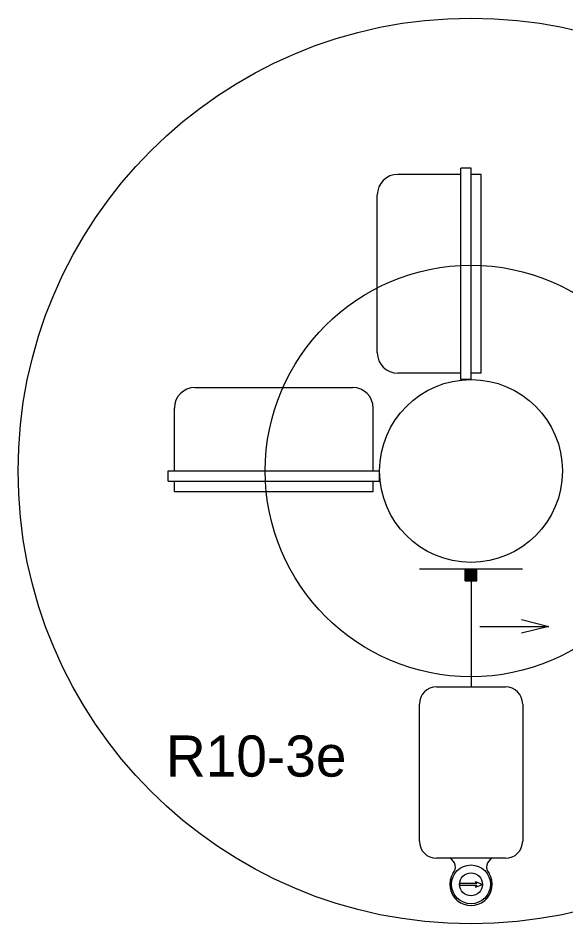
# Model space of a CAD drawing. Extents: x 1369885 to 1370886, y 379976 to 380616.
# Drawn here: x 1370603.9 to 1370663.8, y 380265.3 to 380364.3 of the extents above; entities that cross this region are included whole.
import ezdxf

# ---------------------------------------------------------------- set-up
doc = ezdxf.new("R2010")
doc.units = 0
doc.layers.add('T_Drafting', color=7, linetype='Continuous')

msp = doc.modelspace()

# ---------------------------------------------------------------- linework, layer by layer
at = {"layer": 'T_Drafting'}
for p, q in [((1370652.287, 380347.236), (1370645.412, 380347.236)), ((1370652.287, 380324.799), (1370652.287, 380347.924)), ((1370653.412, 380347.924), (1370652.287, 380347.924)), ((1370653.412, 380324.799), (1370653.412, 380347.924)), ((1370654.537, 380347.236), (1370653.412, 380347.236)), ((1370654.537, 380325.486), (1370654.537, 380347.236)), ((1370643.162, 380327.736), (1370643.162, 380344.986)), ((1370652.287, 380325.486), (1370645.412, 380325.486)), ((1370654.537, 380325.486), (1370653.412, 380325.486)), ((1370653.412, 380324.799), (1370652.287, 380324.799)), ((1370623.225, 380323.924), (1370640.475, 380323.924)), ((1370620.975, 380314.799), (1370620.975, 380321.674)), ((1370642.725, 380314.799), (1370642.725, 380321.674)), ((1370620.287, 380314.799), (1370643.412, 380314.799)), ((1370620.287, 380313.674), (1370620.287, 380314.799)), ((1370643.412, 380313.674), (1370643.412, 380314.799)), ((1370620.287, 380313.674), (1370643.412, 380313.674)), ((1370620.975, 380312.549), (1370620.975, 380313.674)), ((1370642.725, 380312.549), (1370642.725, 380313.674)), ((1370620.975, 380312.549), (1370642.725, 380312.549)), ((1370659.037, 380304.049), (1370647.787, 380304.049)), ((1370652.787, 380302.799), (1370652.787, 380304.049)), ((1370652.787, 380302.808), (1370654.028, 380304.049)), ((1370652.787, 380302.829), (1370654.007, 380304.049)), ((1370652.787, 380302.85), (1370653.986, 380304.049)), ((1370652.787, 380302.871), (1370653.965, 380304.049)), ((1370652.787, 380302.892), (1370653.943, 380304.049)), ((1370652.787, 380302.914), (1370653.922, 380304.049)), ((1370652.787, 380302.935), (1370653.901, 380304.049)), ((1370652.787, 380302.956), (1370653.88, 380304.049)), ((1370652.787, 380302.977), (1370653.859, 380304.049)), ((1370652.787, 380302.998), (1370653.837, 380304.049)), ((1370652.787, 380303.02), (1370653.816, 380304.049)), ((1370652.787, 380303.041), (1370653.795, 380304.049)), ((1370652.787, 380303.062), (1370653.774, 380304.049)), ((1370652.787, 380303.083), (1370653.752, 380304.049)), ((1370652.787, 380303.105), (1370653.731, 380304.049)), ((1370652.787, 380303.126), (1370653.71, 380304.049)), ((1370652.787, 380303.147), (1370653.689, 380304.049)), ((1370652.787, 380303.168), (1370653.668, 380304.049)), ((1370652.787, 380303.189), (1370653.646, 380304.049)), ((1370652.787, 380303.211), (1370653.625, 380304.049)), ((1370652.787, 380303.232), (1370653.604, 380304.049)), ((1370652.787, 380303.253), (1370653.583, 380304.049)), ((1370652.787, 380303.274), (1370653.562, 380304.049)), ((1370652.787, 380303.295), (1370653.54, 380304.049)), ((1370652.787, 380303.317), (1370653.519, 380304.049)), ((1370652.787, 380303.338), (1370653.498, 380304.049)), ((1370652.787, 380303.359), (1370653.477, 380304.049)), ((1370652.787, 380303.38), (1370653.455, 380304.049)), ((1370652.787, 380303.401), (1370653.434, 380304.049)), ((1370652.787, 380303.423), (1370653.413, 380304.049)), ((1370652.787, 380303.444), (1370653.392, 380304.049)), ((1370652.787, 380303.465), (1370653.371, 380304.049)), ((1370652.787, 380303.486), (1370653.349, 380304.049)), ((1370652.787, 380303.508), (1370653.328, 380304.049)), ((1370652.787, 380303.529), (1370653.307, 380304.049)), ((1370652.787, 380303.55), (1370653.286, 380304.049)), ((1370652.787, 380303.571), (1370653.265, 380304.049)), ((1370652.787, 380303.592), (1370653.243, 380304.049)), ((1370652.787, 380303.614), (1370653.222, 380304.049)), ((1370652.787, 380303.635), (1370653.201, 380304.049)), ((1370652.787, 380303.656), (1370653.18, 380304.049)), ((1370652.787, 380303.677), (1370653.158, 380304.049)), ((1370652.787, 380303.698), (1370653.137, 380304.049)), ((1370652.787, 380303.72), (1370653.116, 380304.049)), ((1370652.787, 380303.741), (1370653.095, 380304.049)), ((1370652.787, 380303.762), (1370653.074, 380304.049)), ((1370652.787, 380303.783), (1370653.052, 380304.049)), ((1370652.787, 380303.805), (1370653.031, 380304.049)), ((1370652.787, 380303.826), (1370653.01, 380304.049)), ((1370652.787, 380303.847), (1370652.989, 380304.049)), ((1370652.787, 380303.868), (1370652.968, 380304.049)), ((1370652.787, 380303.889), (1370652.946, 380304.049)), ((1370652.787, 380303.911), (1370652.925, 380304.049)), ((1370652.787, 380303.932), (1370652.904, 380304.049)), ((1370652.787, 380303.953), (1370652.883, 380304.049)), ((1370652.787, 380303.974), (1370652.861, 380304.049)), ((1370652.787, 380303.995), (1370652.84, 380304.049)), ((1370652.787, 380304.017), (1370652.819, 380304.049)), ((1370652.787, 380304.038), (1370652.798, 380304.049)), ((1370652.799, 380302.799), (1370654.037, 380304.036)), ((1370652.821, 380302.799), (1370654.037, 380304.015)), ((1370652.842, 380302.799), (1370654.037, 380303.994)), ((1370652.863, 380302.799), (1370654.037, 380303.973)), ((1370652.884, 380302.799), (1370654.037, 380303.951)), ((1370652.906, 380302.799), (1370654.037, 380303.93)), ((1370652.927, 380302.799), (1370654.037, 380303.909)), ((1370652.948, 380302.799), (1370654.037, 380303.888)), ((1370652.969, 380302.799), (1370654.037, 380303.867)), ((1370652.99, 380302.799), (1370654.037, 380303.845)), ((1370653.012, 380302.799), (1370654.037, 380303.824)), ((1370653.033, 380302.799), (1370654.037, 380303.803)), ((1370653.054, 380302.799), (1370654.037, 380303.782)), ((1370653.075, 380302.799), (1370654.037, 380303.761)), ((1370653.096, 380302.799), (1370654.037, 380303.739)), ((1370653.118, 380302.799), (1370654.037, 380303.718)), ((1370653.139, 380302.799), (1370654.037, 380303.697)), ((1370653.16, 380302.799), (1370654.037, 380303.676)), ((1370653.181, 380302.799), (1370654.037, 380303.654)), ((1370654.037, 380302.799), (1370654.037, 380304.049)), ((1370652.787, 380302.799), (1370654.037, 380302.799)), ((1370653.202, 380302.799), (1370654.037, 380303.633)), ((1370653.224, 380302.799), (1370654.037, 380303.612)), ((1370653.245, 380302.799), (1370654.037, 380303.591)), ((1370653.266, 380302.799), (1370654.037, 380303.57)), ((1370653.287, 380302.799), (1370654.037, 380303.548)), ((1370653.309, 380302.799), (1370654.037, 380303.527)), ((1370653.33, 380302.799), (1370654.037, 380303.506)), ((1370653.351, 380302.799), (1370654.037, 380303.485)), ((1370653.372, 380302.799), (1370654.037, 380303.464)), ((1370653.393, 380302.799), (1370654.037, 380303.442)), ((1370653.412, 380302.799), (1370653.412, 380291.194)), ((1370653.415, 380302.799), (1370654.037, 380303.421)), ((1370653.436, 380302.799), (1370654.037, 380303.4)), ((1370653.457, 380302.799), (1370654.037, 380303.379)), ((1370653.478, 380302.799), (1370654.037, 380303.357)), ((1370653.499, 380302.799), (1370654.037, 380303.336)), ((1370653.521, 380302.799), (1370654.037, 380303.315)), ((1370653.542, 380302.799), (1370654.037, 380303.294)), ((1370653.563, 380302.799), (1370654.037, 380303.273)), ((1370653.584, 380302.799), (1370654.037, 380303.251)), ((1370653.606, 380302.799), (1370654.037, 380303.23)), ((1370653.627, 380302.799), (1370654.037, 380303.209)), ((1370653.648, 380302.799), (1370654.037, 380303.188)), ((1370653.669, 380302.799), (1370654.037, 380303.167)), ((1370653.69, 380302.799), (1370654.037, 380303.145)), ((1370653.712, 380302.799), (1370654.037, 380303.124)), ((1370653.733, 380302.799), (1370654.037, 380303.103)), ((1370653.754, 380302.799), (1370654.037, 380303.082)), ((1370653.775, 380302.799), (1370654.037, 380303.061)), ((1370653.796, 380302.799), (1370654.037, 380303.039)), ((1370653.818, 380302.799), (1370654.037, 380303.018)), ((1370653.839, 380302.799), (1370654.037, 380302.997)), ((1370653.86, 380302.799), (1370654.037, 380302.976)), ((1370653.881, 380302.799), (1370654.037, 380302.954)), ((1370653.903, 380302.799), (1370654.037, 380302.933)), ((1370653.924, 380302.799), (1370654.037, 380302.912)), ((1370653.945, 380302.799), (1370654.037, 380302.891)), ((1370653.966, 380302.799), (1370654.037, 380302.87)), ((1370653.987, 380302.799), (1370654.037, 380302.848)), ((1370654.009, 380302.799), (1370654.037, 380302.827)), ((1370654.03, 380302.799), (1370654.037, 380302.806)), ((1370654.379, 380297.797), (1370661.928, 380297.797)), ((1370649.638, 380291.194), (1370657.187, 380291.194)), ((1370647.763, 380274.319), (1370647.763, 380289.319)), ((1370659.062, 380289.319), (1370659.062, 380274.319)), ((1370657.187, 380272.444), (1370649.638, 380272.444)), ((1370652.171, 380269.707), (1370652.171, 380269.482)), ((1370654.053, 380269.707), (1370652.171, 380269.707)), ((1370654.053, 380269.482), (1370652.171, 380269.482)), ((1370653.903, 380269.894), (1370654.662, 380269.594)), ((1370654.053, 380269.707), (1370653.903, 380269.894)), ((1370653.903, 380269.294), (1370654.662, 380269.594)), ((1370653.903, 380269.294), (1370654.053, 380269.482))]:
    msp.add_line(p, q, dxfattribs=at)
msp.add_lwpolyline([(1370658.928, 380298.547), (1370661.928, 380297.797), (1370658.928, 380297.047)], dxfattribs=at)
for centre, radius in [((1370653.412, 380314.799), 49.525), ((1370653.412, 380314.799), 22.5), ((1370653.412, 380314.799), 10), ((1370653.412, 380269.594), 2.125), ((1370653.412, 380269.594), 1.25)]:
    msp.add_circle(centre, radius, dxfattribs=at)
for centre, radius, start, end in [((1370645.412, 380344.986), 2.25, 90, 180), ((1370645.412, 380327.736), 2.25, 180, 270), ((1370623.225, 380321.674), 2.25, 90, 180), ((1370640.475, 380321.674), 2.25, 360, 90), ((1370649.638, 380289.319), 1.875, 90, 180), ((1370657.187, 380289.319), 1.875, 0, 90), ((1370649.638, 380274.319), 1.875, 180, 270), ((1370657.187, 380274.319), 1.875, 270, 0), ((1370650.653, 380271.494), 1.05, 318.19721, 64.80442), ((1370656.172, 380271.494), 1.05, 115.19558, 221.80279), ((1370653.412, 380269.594), 2.313, 148.74024, 227.49336), ((1370653.412, 380269.594), 2.313, 148.74024, 31.25976), ((1370653.412, 380269.594), 2.313, 312.50664, 31.25976)]:
    msp.add_arc(centre, radius, start, end, dxfattribs=at)

# ---------------------------------------------------------------- texts
msp.add_text('R10-3e', height=4.5, dxfattribs=at).set_placement((1370620.055, 380281.378))

doc.saveas('drawing.dxf')
